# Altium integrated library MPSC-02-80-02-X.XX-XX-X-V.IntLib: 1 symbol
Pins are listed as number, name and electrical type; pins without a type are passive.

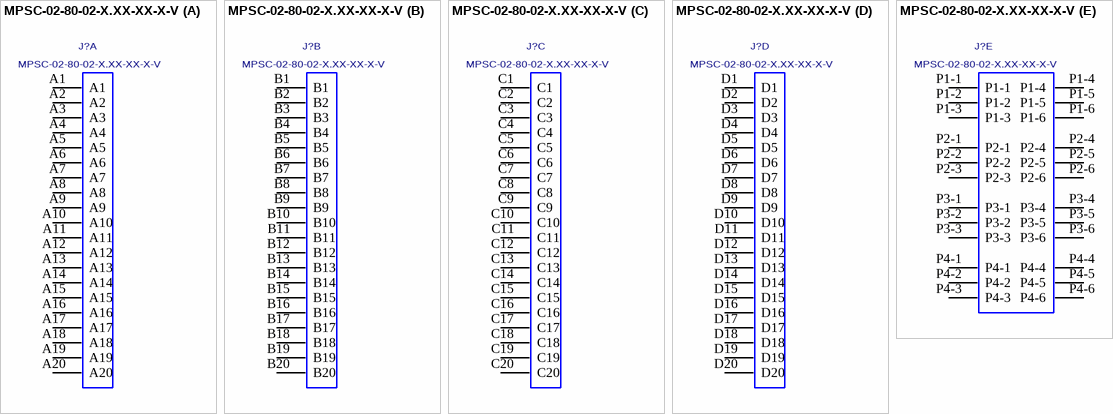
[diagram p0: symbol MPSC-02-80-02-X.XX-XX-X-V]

## MPSC-02-80-02-X.XX-XX-X-V
designator J?
VERTICAL MINI-POWER W/ SIGNAL SOCKET.; MANUFACTURER: SAMTEC
footprint MPSC-02-80-02-X.XX-XX-X-V
part A pins: A1, A2, A3, A4, A5, A6, A7, A8, A9, A10, A11, A12, A13, A14, A15, A16, A17, A18, A19, A20
part B pins: B1, B2, B3, B4, B5, B6, B7, B8, B9, B10, B11, B12, B13, B14, B15, B16, B17, B18, B19, B20
part C pins: C1, C2, C3, C4, C5, C6, C7, C8, C9, C10, C11, C12, C13, C14, C15, C16, C17, C18, C19, C20
part D pins: D1, D2, D3, D4, D5, D6, D7, D8, D9, D10, D11, D12, D13, D14, D15, D16, D17, D18, D19, D20
part E pins: P1-1, P1-2, P1-3, P1-4, P1-5, P1-6, P2-1, P2-2, P2-3, P2-4, P2-5, P2-6, P3-1, P3-2, P3-3, P3-4, P3-5, P3-6, P4-1, P4-2, P4-3, P4-4, P4-5, P4-6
